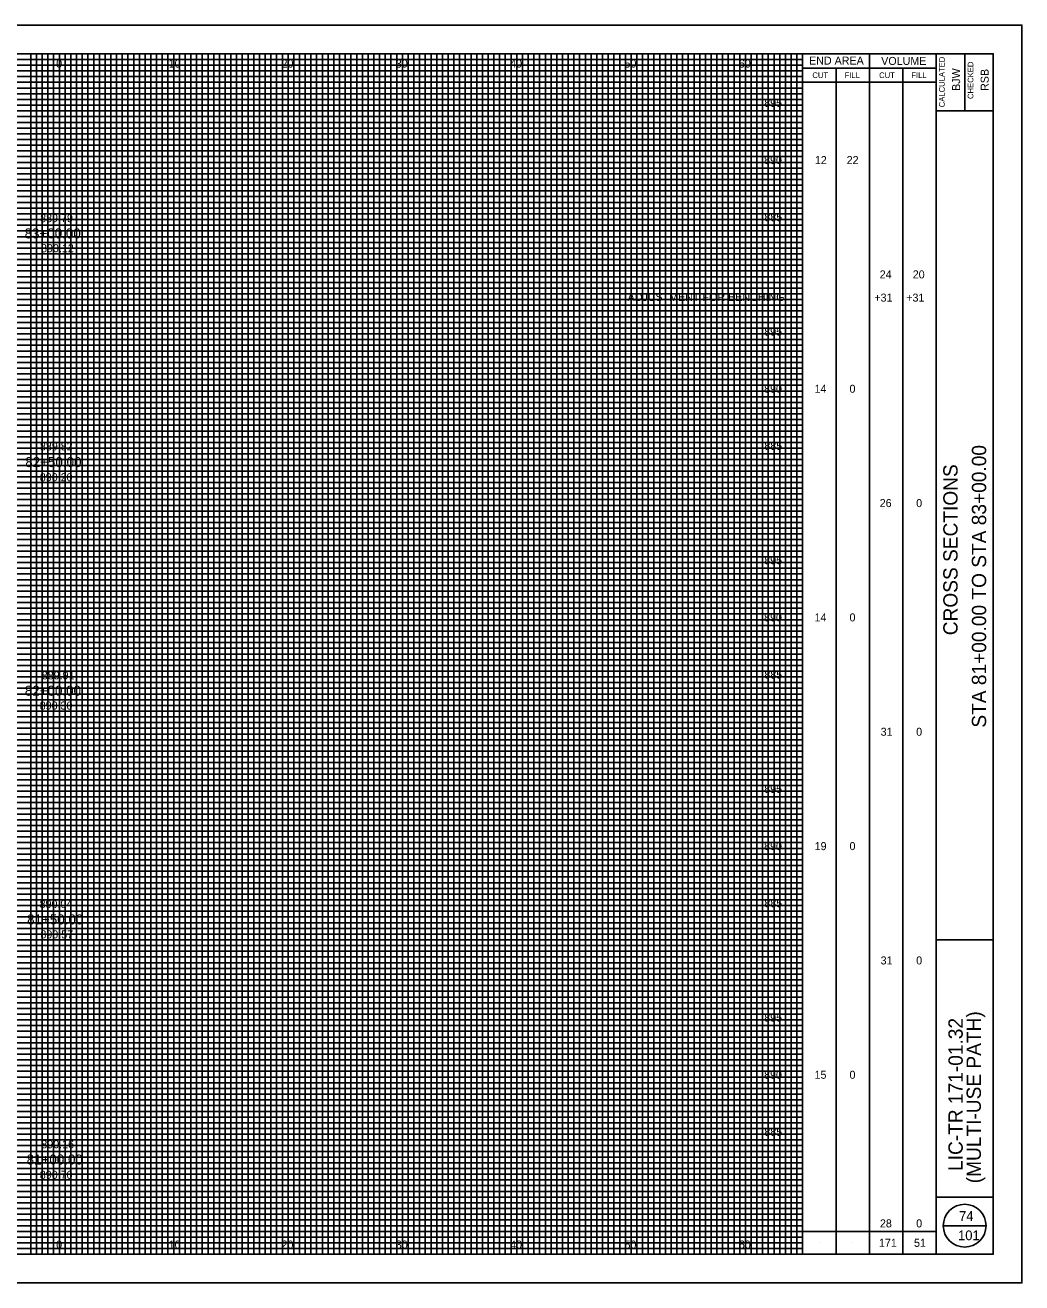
# Model space of a CAD drawing. Extents: x -10 to 160, y -2 to 3672.
# Drawn here: x 72.8 to 160, y 572.5 to 682.5 of the extents above; entities that cross this region are included whole.
import ezdxf

# ---------------------------------------------------------------- set-up
doc = ezdxf.new("R2010")
doc.units = 0
for name, color, linetype in [('SH_Border', 7, 'Continuous'), ('SH_Cut_Line', 7, 'Continuous'), ('SH_Data', 7, 'Continuous'), ('SH_Major_Grid_Line', 7, 'Continuous'), ('SH_Minor_Grid_Line', 7, 'Continuous'), ('SH_Text', 7, 'Continuous'), ('TX_P_10', 7, 'Continuous'), ('TX_X_10', 7, 'Continuous')]:
    doc.layers.add(name, color=color, linetype=linetype)

msp = doc.modelspace()

# ---------------------------------------------------------------- linework, layer by layer
at = {"layer": 'SH_Border'}
for p, q in [((152.5, 575), (152.5, 680)), ((155, 680), (155, 675)), ((152.5, 675), (157.5, 675)), ((152.5, 602.5), (157.5, 602.5)), ((152.5, 580), (157.5, 580))]:
    msp.add_line(p, q, dxfattribs=at)
msp.add_lwpolyline([(0, 680), (157.5, 680), (157.5, 575), (0, 575)], close=True, dxfattribs=at)
at = {"layer": 'SH_Cut_Line'}
msp.add_lwpolyline([(-10, 572.5), (160, 572.5), (160, 682.5), (-10, 682.5)], close=True, dxfattribs=at)
at = {"layer": 'SH_Data'}
for p, q in [((140.83, 575), (140.83, 680)), ((146.67, 575), (146.67, 680)), ((140.83, 678.75), (152.5, 678.75)), ((143.75, 575), (143.75, 678.75)), ((149.58, 575), (149.58, 678.75)), ((140.83, 677.5), (152.5, 677.5)), ((153.12, 577.5), (156.88, 577.5)), ((140.83, 577), (152.5, 577)), ((142.29, 576), (142.29, 576)), ((145.21, 576), (145.21, 576)), ((148.12, 576), (148.12, 576)), ((151.04, 576), (151.04, 576))]:
    msp.add_line(p, q, dxfattribs=at)
msp.add_circle((155, 577.5), 1.87, dxfattribs=at)
at = {"layer": 'SH_Major_Grid_Line'}
for p, q in [((75.83, 575), (75.83, 680)), ((80.83, 575), (80.83, 680)), ((85.83, 575), (85.83, 680)), ((90.83, 575), (90.83, 680)), ((95.83, 575), (95.83, 680)), ((100.83, 575), (100.83, 680)), ((105.83, 575), (105.83, 680)), ((110.83, 575), (110.83, 680)), ((115.83, 575), (115.83, 680)), ((120.83, 575), (120.83, 680)), ((125.83, 575), (125.83, 680)), ((130.83, 575), (130.83, 680)), ((135.83, 575), (135.83, 680)), ((5.83, 675), (140.83, 675)), ((5.83, 670), (140.83, 670)), ((5.83, 665), (140.83, 665)), ((5.83, 660), (140.83, 660)), ((5.83, 655), (140.83, 655)), ((5.83, 650), (140.83, 650)), ((5.83, 645), (140.83, 645)), ((5.83, 640), (140.83, 640)), ((5.83, 635), (140.83, 635)), ((5.83, 630), (140.83, 630)), ((5.83, 625), (140.83, 625)), ((5.83, 620), (140.83, 620)), ((5.83, 615), (140.83, 615)), ((5.83, 610), (140.83, 610)), ((5.83, 605), (140.83, 605)), ((5.83, 600), (140.83, 600)), ((5.83, 595), (140.83, 595)), ((5.83, 590), (140.83, 590)), ((5.83, 585), (140.83, 585)), ((5.83, 580), (140.83, 580))]:
    msp.add_line(p, q, dxfattribs=at)
at = {"layer": 'SH_Minor_Grid_Line'}
for p, q in [((73.33, 575), (73.33, 680)), ((73.83, 575), (73.83, 680)), ((74.33, 575), (74.33, 680)), ((74.83, 575), (74.83, 680)), ((75.33, 575), (75.33, 680)), ((76.33, 575), (76.33, 680)), ((76.83, 575), (76.83, 680)), ((77.33, 575), (77.33, 680)), ((77.83, 575), (77.83, 680)), ((78.33, 575), (78.33, 680)), ((78.83, 575), (78.83, 680)), ((79.33, 575), (79.33, 680)), ((79.83, 575), (79.83, 680)), ((80.33, 575), (80.33, 680)), ((81.33, 575), (81.33, 680)), ((81.83, 575), (81.83, 680)), ((82.33, 575), (82.33, 680)), ((82.83, 575), (82.83, 680)), ((83.33, 575), (83.33, 680)), ((83.83, 575), (83.83, 680)), ((84.33, 575), (84.33, 680)), ((84.83, 575), (84.83, 680)), ((85.33, 575), (85.33, 680)), ((86.33, 575), (86.33, 680)), ((86.83, 575), (86.83, 680)), ((87.33, 575), (87.33, 680)), ((87.83, 575), (87.83, 680)), ((88.33, 575), (88.33, 680)), ((88.83, 575), (88.83, 680)), ((89.33, 575), (89.33, 680)), ((89.83, 575), (89.83, 680)), ((90.33, 575), (90.33, 680)), ((91.33, 575), (91.33, 680)), ((91.83, 575), (91.83, 680)), ((92.33, 575), (92.33, 680)), ((92.83, 575), (92.83, 680)), ((93.33, 575), (93.33, 680)), ((93.83, 575), (93.83, 680)), ((94.33, 575), (94.33, 680)), ((94.83, 575), (94.83, 680)), ((95.33, 575), (95.33, 680)), ((96.33, 575), (96.33, 680)), ((96.83, 575), (96.83, 680)), ((97.33, 575), (97.33, 680)), ((97.83, 575), (97.83, 680)), ((98.33, 575), (98.33, 680)), ((98.83, 575), (98.83, 680)), ((99.33, 575), (99.33, 680)), ((99.83, 575), (99.83, 680)), ((100.33, 575), (100.33, 680)), ((101.33, 575), (101.33, 680)), ((101.83, 575), (101.83, 680)), ((102.33, 575), (102.33, 680)), ((102.83, 575), (102.83, 680)), ((103.33, 575), (103.33, 680)), ((103.83, 575), (103.83, 680)), ((104.33, 575), (104.33, 680)), ((104.83, 575), (104.83, 680)), ((105.33, 575), (105.33, 680)), ((106.33, 575), (106.33, 680)), ((106.83, 575), (106.83, 680)), ((107.33, 575), (107.33, 680)), ((107.83, 575), (107.83, 680)), ((108.33, 575), (108.33, 680)), ((108.83, 575), (108.83, 680)), ((109.33, 575), (109.33, 680)), ((109.83, 575), (109.83, 680)), ((110.33, 575), (110.33, 680)), ((111.33, 575), (111.33, 680)), ((111.83, 575), (111.83, 680)), ((112.33, 575), (112.33, 680)), ((112.83, 575), (112.83, 680)), ((113.33, 575), (113.33, 680)), ((113.83, 575), (113.83, 680)), ((114.33, 575), (114.33, 680)), ((114.83, 575), (114.83, 680)), ((115.33, 575), (115.33, 680)), ((116.33, 575), (116.33, 680)), ((116.83, 575), (116.83, 680)), ((117.33, 575), (117.33, 680)), ((117.83, 575), (117.83, 680)), ((118.33, 575), (118.33, 680)), ((118.83, 575), (118.83, 680)), ((119.33, 575), (119.33, 680)), ((119.83, 575), (119.83, 680)), ((120.33, 575), (120.33, 680)), ((121.33, 575), (121.33, 680)), ((121.83, 575), (121.83, 680)), ((122.33, 575), (122.33, 680)), ((122.83, 575), (122.83, 680)), ((123.33, 575), (123.33, 680)), ((123.83, 575), (123.83, 680)), ((124.33, 575), (124.33, 680)), ((124.83, 575), (124.83, 680)), ((125.33, 575), (125.33, 680)), ((126.33, 575), (126.33, 680)), ((126.83, 575), (126.83, 680)), ((127.33, 575), (127.33, 680)), ((127.83, 575), (127.83, 680)), ((128.33, 575), (128.33, 680)), ((128.83, 575), (128.83, 680)), ((129.33, 575), (129.33, 680)), ((129.83, 575), (129.83, 680)), ((130.33, 575), (130.33, 680)), ((131.33, 575), (131.33, 680)), ((131.83, 575), (131.83, 680)), ((132.33, 575), (132.33, 680)), ((132.83, 575), (132.83, 680)), ((133.33, 575), (133.33, 680)), ((133.83, 575), (133.83, 680)), ((134.33, 575), (134.33, 680)), ((134.83, 575), (134.83, 680)), ((135.33, 575), (135.33, 680)), ((136.33, 575), (136.33, 680)), ((136.83, 575), (136.83, 680)), ((137.33, 575), (137.33, 680)), ((137.83, 575), (137.83, 680)), ((138.33, 575), (138.33, 680)), ((138.83, 575), (138.83, 680)), ((139.33, 575), (139.33, 680)), ((139.83, 575), (139.83, 680)), ((140.33, 575), (140.33, 680)), ((5.83, 679.5), (140.83, 679.5)), ((5.83, 679), (140.83, 679)), ((5.83, 678.5), (140.83, 678.5)), ((5.83, 678), (140.83, 678)), ((5.83, 677.5), (140.83, 677.5)), ((5.83, 677), (140.83, 677)), ((5.83, 676.5), (140.83, 676.5)), ((5.83, 676), (140.83, 676)), ((5.83, 675.5), (140.83, 675.5)), ((5.83, 674.5), (140.83, 674.5)), ((5.83, 674), (140.83, 674)), ((5.83, 673.5), (140.83, 673.5)), ((5.83, 673), (140.83, 673)), ((5.83, 672.5), (140.83, 672.5)), ((5.83, 672), (140.83, 672)), ((5.83, 671.5), (140.83, 671.5)), ((5.83, 671), (140.83, 671)), ((5.83, 670.5), (140.83, 670.5)), ((5.83, 669.5), (140.83, 669.5)), ((5.83, 669), (140.83, 669)), ((5.83, 668.5), (140.83, 668.5)), ((5.83, 668), (140.83, 668)), ((5.83, 667.5), (140.83, 667.5)), ((5.83, 667), (140.83, 667)), ((5.83, 666.5), (140.83, 666.5)), ((5.83, 666), (140.83, 666)), ((5.83, 665.5), (140.83, 665.5)), ((5.83, 664.5), (140.83, 664.5)), ((5.83, 664), (140.83, 664)), ((5.83, 663.5), (140.83, 663.5)), ((5.83, 663), (140.83, 663)), ((5.83, 662.5), (140.83, 662.5)), ((5.83, 662), (140.83, 662)), ((5.83, 661.5), (140.83, 661.5)), ((5.83, 661), (140.83, 661)), ((5.83, 660.5), (140.83, 660.5)), ((5.83, 659.5), (140.83, 659.5)), ((5.83, 659), (140.83, 659)), ((5.83, 658.5), (140.83, 658.5)), ((5.83, 658), (140.83, 658)), ((5.83, 657.5), (140.83, 657.5)), ((5.83, 657), (140.83, 657)), ((5.83, 656.5), (140.83, 656.5)), ((5.83, 656), (140.83, 656)), ((5.83, 655.5), (140.83, 655.5)), ((5.83, 654.5), (140.83, 654.5)), ((5.83, 654), (140.83, 654)), ((5.83, 653.5), (140.83, 653.5)), ((5.83, 653), (140.83, 653)), ((5.83, 652.5), (140.83, 652.5)), ((5.83, 652), (140.83, 652)), ((5.83, 651.5), (140.83, 651.5)), ((5.83, 651), (140.83, 651)), ((5.83, 650.5), (140.83, 650.5)), ((5.83, 649.5), (140.83, 649.5)), ((5.83, 649), (140.83, 649)), ((5.83, 648.5), (140.83, 648.5)), ((5.83, 648), (140.83, 648)), ((5.83, 647.5), (140.83, 647.5)), ((5.83, 647), (140.83, 647)), ((5.83, 646.5), (140.83, 646.5)), ((5.83, 646), (140.83, 646)), ((5.83, 645.5), (140.83, 645.5)), ((5.83, 644.5), (140.83, 644.5)), ((5.83, 644), (140.83, 644)), ((5.83, 643.5), (140.83, 643.5)), ((5.83, 643), (140.83, 643)), ((5.83, 642.5), (140.83, 642.5)), ((5.83, 642), (140.83, 642)), ((5.83, 641.5), (140.83, 641.5)), ((5.83, 641), (140.83, 641)), ((5.83, 640.5), (140.83, 640.5)), ((5.83, 639.5), (140.83, 639.5)), ((5.83, 639), (140.83, 639)), ((5.83, 638.5), (140.83, 638.5)), ((5.83, 638), (140.83, 638)), ((5.83, 637.5), (140.83, 637.5)), ((5.83, 637), (140.83, 637)), ((5.83, 636.5), (140.83, 636.5)), ((5.83, 636), (140.83, 636)), ((5.83, 635.5), (140.83, 635.5)), ((5.83, 634.5), (140.83, 634.5)), ((5.83, 634), (140.83, 634)), ((5.83, 633.5), (140.83, 633.5)), ((5.83, 633), (140.83, 633)), ((5.83, 632.5), (140.83, 632.5)), ((5.83, 632), (140.83, 632)), ((5.83, 631.5), (140.83, 631.5)), ((5.83, 631), (140.83, 631)), ((5.83, 630.5), (140.83, 630.5)), ((5.83, 629.5), (140.83, 629.5)), ((5.83, 629), (140.83, 629)), ((5.83, 628.5), (140.83, 628.5)), ((5.83, 628), (140.83, 628)), ((5.83, 627.5), (140.83, 627.5)), ((5.83, 627), (140.83, 627)), ((5.83, 626.5), (140.83, 626.5)), ((5.83, 626), (140.83, 626)), ((5.83, 625.5), (140.83, 625.5)), ((5.83, 624.5), (140.83, 624.5)), ((5.83, 624), (140.83, 624)), ((5.83, 623.5), (140.83, 623.5)), ((5.83, 623), (140.83, 623)), ((5.83, 622.5), (140.83, 622.5)), ((5.83, 622), (140.83, 622)), ((5.83, 621.5), (140.83, 621.5)), ((5.83, 621), (140.83, 621)), ((5.83, 620.5), (140.83, 620.5)), ((5.83, 619.5), (140.83, 619.5)), ((5.83, 619), (140.83, 619)), ((5.83, 618.5), (140.83, 618.5)), ((5.83, 618), (140.83, 618)), ((5.83, 617.5), (140.83, 617.5)), ((5.83, 617), (140.83, 617)), ((5.83, 616.5), (140.83, 616.5)), ((5.83, 616), (140.83, 616)), ((5.83, 615.5), (140.83, 615.5)), ((5.83, 614.5), (140.83, 614.5)), ((5.83, 614), (140.83, 614)), ((5.83, 613.5), (140.83, 613.5)), ((5.83, 613), (140.83, 613)), ((5.83, 612.5), (140.83, 612.5)), ((5.83, 612), (140.83, 612)), ((5.83, 611.5), (140.83, 611.5)), ((5.83, 611), (140.83, 611)), ((5.83, 610.5), (140.83, 610.5)), ((5.83, 609.5), (140.83, 609.5)), ((5.83, 609), (140.83, 609)), ((5.83, 608.5), (140.83, 608.5)), ((5.83, 608), (140.83, 608)), ((5.83, 607.5), (140.83, 607.5)), ((5.83, 607), (140.83, 607)), ((5.83, 606.5), (140.83, 606.5)), ((5.83, 606), (140.83, 606)), ((5.83, 605.5), (140.83, 605.5)), ((5.83, 604.5), (140.83, 604.5)), ((5.83, 604), (140.83, 604)), ((5.83, 603.5), (140.83, 603.5)), ((5.83, 603), (140.83, 603)), ((5.83, 602.5), (140.83, 602.5)), ((5.83, 602), (140.83, 602)), ((5.83, 601.5), (140.83, 601.5)), ((5.83, 601), (140.83, 601)), ((5.83, 600.5), (140.83, 600.5)), ((5.83, 599.5), (140.83, 599.5)), ((5.83, 599), (140.83, 599)), ((5.83, 598.5), (140.83, 598.5)), ((5.83, 598), (140.83, 598)), ((5.83, 597.5), (140.83, 597.5)), ((5.83, 597), (140.83, 597)), ((5.83, 596.5), (140.83, 596.5)), ((5.83, 596), (140.83, 596)), ((5.83, 595.5), (140.83, 595.5)), ((5.83, 594.5), (140.83, 594.5)), ((5.83, 594), (140.83, 594)), ((5.83, 593.5), (140.83, 593.5)), ((5.83, 593), (140.83, 593)), ((5.83, 592.5), (140.83, 592.5)), ((5.83, 592), (140.83, 592)), ((5.83, 591.5), (140.83, 591.5)), ((5.83, 591), (140.83, 591)), ((5.83, 590.5), (140.83, 590.5)), ((5.83, 589.5), (140.83, 589.5)), ((5.83, 589), (140.83, 589)), ((5.83, 588.5), (140.83, 588.5)), ((5.83, 588), (140.83, 588)), ((5.83, 587.5), (140.83, 587.5)), ((5.83, 587), (140.83, 587)), ((5.83, 586.5), (140.83, 586.5)), ((5.83, 586), (140.83, 586)), ((5.83, 585.5), (140.83, 585.5)), ((5.83, 584.5), (140.83, 584.5)), ((5.83, 584), (140.83, 584)), ((5.83, 583.5), (140.83, 583.5)), ((5.83, 583), (140.83, 583)), ((5.83, 582.5), (140.83, 582.5)), ((5.83, 582), (140.83, 582)), ((5.83, 581.5), (140.83, 581.5)), ((5.83, 581), (140.83, 581)), ((5.83, 580.5), (140.83, 580.5)), ((5.83, 579.5), (140.83, 579.5)), ((5.83, 579), (140.83, 579)), ((5.83, 578.5), (140.83, 578.5)), ((5.83, 578), (140.83, 578)), ((5.83, 577.5), (140.83, 577.5)), ((5.83, 577), (140.83, 577)), ((5.83, 576.5), (140.83, 576.5)), ((5.83, 576), (140.83, 576)), ((5.83, 575.5), (140.83, 575.5))]:
    msp.add_line(p, q, dxfattribs=at)

# ---------------------------------------------------------------- texts
at = {"layer": 'SH_Data'}
for s, height, p in [('END AREA', 0.7, (141.39, 679.05)), ('VOLUME', 0.7, (147.7, 679.02)), ('CUT', 0.5, (141.68, 677.87)), ('FILL', 0.5, (144.5, 677.87)), ('CUT', 0.5, (147.52, 677.87)), ('FILL', 0.5, (150.34, 677.87)), ('74', 0.85, (154.51, 577.92)), ('101', 0.85, (154.42, 576.23))]:
    msp.add_text(s, height=height, dxfattribs=at).set_placement(p)
for s, height, p in [('CALCULATED', 0.5, (153.26, 675.32)), ('BJW', 0.7, (154.6, 676.75)), ('CHECKED', 0.5, (155.76, 676.04)), ('RSB', 0.7, (157.1, 676.75)), ('STA 81+00.00 TO STA 83+00.00', 1.25, (156.88, 621.06)), ('CROSS SECTIONS', 1.25, (154.38, 629.14)), ('LIC-TR 171-01.32', 1.25, (154.83, 582.29)), ('(MULTI-USE PATH)', 1.25, (156.42, 581.21))]:
    msp.add_text(s, height=height, rotation=90, dxfattribs=at).set_placement(p)
at = {"layer": 'SH_Text'}
for s, height, p in [('0', 0.7, (75.55, 678.79)), ('10', 0.7, (85.39, 678.79)), ('20', 0.7, (95.26, 678.79)), ('30', 0.7, (105.25, 678.79)), ('40', 0.7, (115.25, 678.79)), ('50', 0.7, (125.25, 678.79)), ('60', 0.7, (135.25, 678.79)), ('895', 0.7, (137.47, 675.35)), ('890', 0.7, (137.46, 670.35)), ('12', 0.7, (141.9, 670.35)), ('22', 0.7, (144.68, 670.35)), ('885', 0.7, (137.48, 665.35)), ('83+00.00', 0.875, (72.79, 663.85)), ('24', 0.7, (147.57, 660.35)), ('20', 0.7, (150.46, 660.35)), ('ADJUSTMENT FOR BENCHING', 0.7, (125.52, 658.37)), ('+31', 0.7, (147.1, 658.32)), ('+31', 0.7, (149.89, 658.32)), ('895', 0.7, (137.47, 655.35)), ('890', 0.7, (137.46, 650.35)), ('14', 0.7, (141.87, 650.35)), ('0', 0.7, (144.93, 650.35)), ('885', 0.7, (137.48, 645.35)), ('82+50.00', 0.875, (72.85, 643.85)), ('26', 0.7, (147.57, 640.35)), ('0', 0.7, (150.76, 640.35)), ('895', 0.7, (137.47, 635.35)), ('890', 0.7, (137.46, 630.35)), ('14', 0.7, (141.87, 630.35)), ('0', 0.7, (144.93, 630.35)), ('885', 0.7, (137.48, 625.35)), ('82+00.00', 0.875, (72.81, 623.85)), ('31', 0.7, (147.65, 620.35)), ('0', 0.7, (150.76, 620.35)), ('895', 0.7, (137.47, 615.35)), ('890', 0.7, (137.46, 610.35)), ('19', 0.7, (141.88, 610.35)), ('0', 0.7, (144.93, 610.35)), ('885', 0.7, (137.48, 605.35)), ('81+50.00', 0.875, (73.01, 603.85)), ('31', 0.7, (147.65, 600.35)), ('0', 0.7, (150.76, 600.35)), ('895', 0.7, (137.47, 595.35)), ('890', 0.7, (137.46, 590.35)), ('15', 0.7, (141.87, 590.35)), ('0', 0.7, (144.93, 590.35)), ('885', 0.7, (137.48, 585.35)), ('81+00.00', 0.875, (72.97, 582.85)), ('28', 0.7, (147.59, 577.35)), ('0', 0.7, (150.76, 577.35)), ('0', 0.7, (75.55, 575.5)), ('10', 0.7, (85.39, 575.5)), ('20', 0.7, (95.26, 575.5)), ('30', 0.7, (105.25, 575.5)), ('40', 0.7, (115.25, 575.5)), ('50', 0.7, (125.25, 575.5)), ('60', 0.7, (135.25, 575.5)), ('171', 0.7, (147.5, 575.65)), ('51', 0.7, (150.57, 575.65))]:
    msp.add_text(s, height=height, dxfattribs=at).set_placement(p)
at = {"layer": 'TX_P_10'}
for s, p in [('889.79', (74.15, 665.27)), ('889.82', (74.13, 645.31)), ('889.91', (74.29, 625.28)), ('890.04', (74.1, 605.28)), ('890.16', (74.25, 584.27))]:
    msp.add_text(s, height=0.7, dxfattribs=at).set_placement(p)
at = {"layer": 'TX_X_10'}
for s, p in [('890.12', (74.23, 662.64)), ('890.20', (74.12, 642.61)), ('890.30', (74.11, 622.64)), ('890.57', (74.17, 602.63)), ('890.70', (74.12, 581.6))]:
    msp.add_text(s, height=0.7, dxfattribs=at).set_placement(p)

doc.saveas('drawing.dxf')
